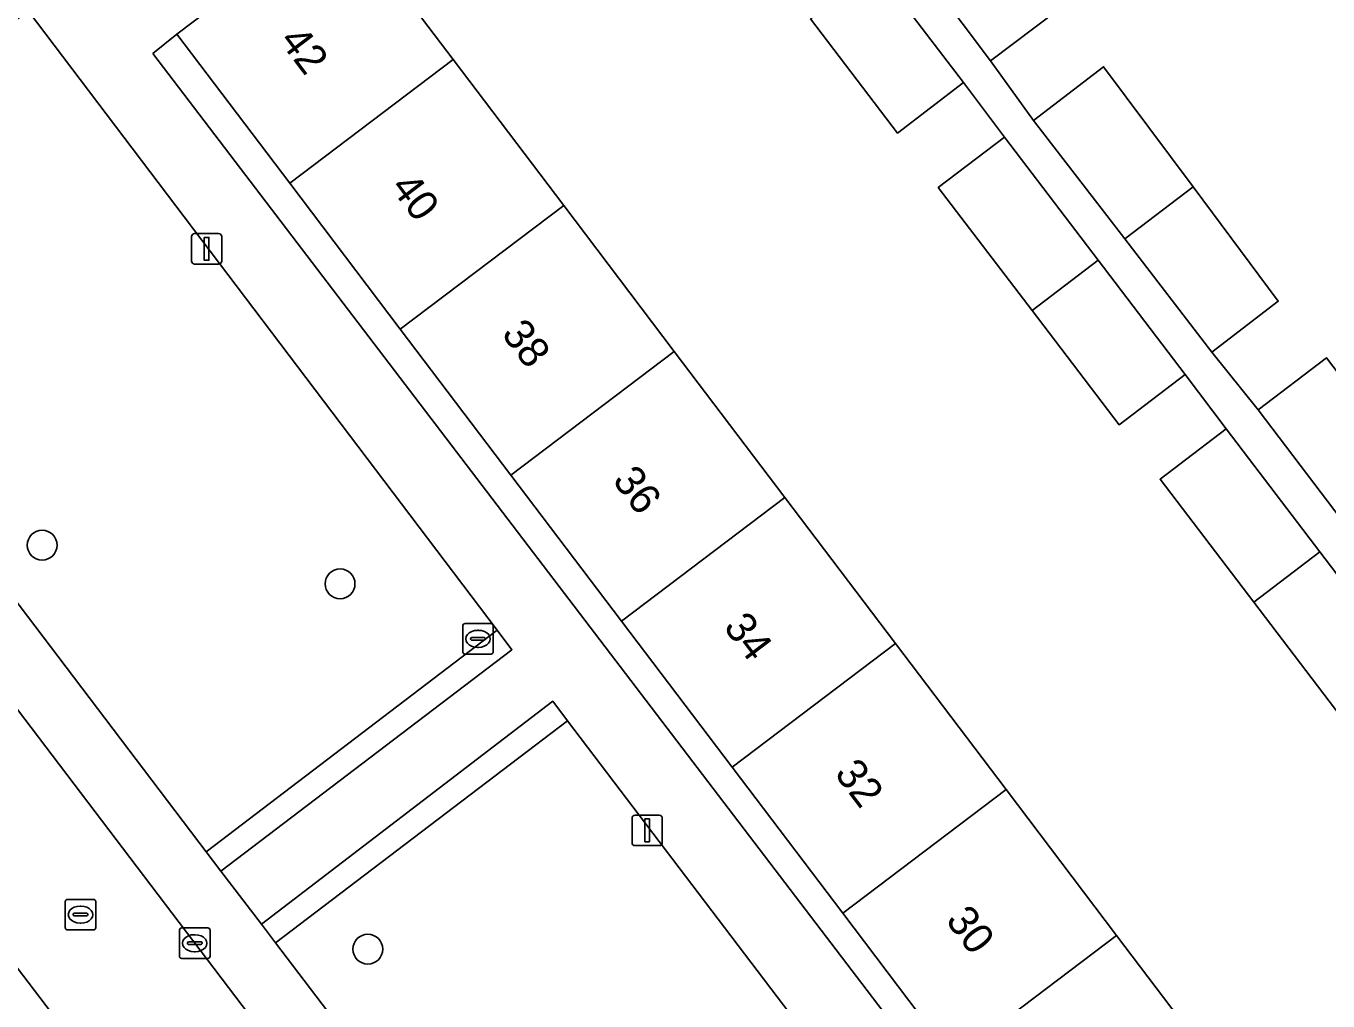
# Model space of a CAD drawing. Extents: x 160030 to 160839, y 385325 to 386450.
# Drawn here: x 160322.65 to 160365.28, y 385818.69 to 385850.63 of the extents above; entities that cross this region are included whole.
import ezdxf

# ---------------------------------------------------------------- set-up
doc = ezdxf.new("R2010")
doc.units = 0
for name, color, linetype in [('IMGEO_Boom', 7, 'Continuous'), ('IMGEO_Erf', 7, 'Continuous'), ('IMGEO_Groenvoorziening', 7, 'Continuous'), ('IMGEO_Haag', 7, 'Continuous'), ('IMGEO_Kolk', 7, 'Continuous'), ('IMGEO_Lichtmast', 7, 'Continuous'), ('IMGEO_Pand', 7, 'Continuous'), ('IMGEO_Pand_nummerreeks', 7, 'Continuous'), ('IMGEO_Parkeervlak_open', 7, 'Continuous'), ('IMGEO_Rijbaan_lokaal_open', 7, 'Continuous'), ('IMGEO_Rioolput', 7, 'Continuous'), ('IMGEO_Voetpad_open', 7, 'Continuous')]:
    doc.layers.add(name, color=color, linetype=linetype)

msp = doc.modelspace()

# ---------------------------------------------------------------- linework, layer by layer
at = {"layer": 'IMGEO_Boom'}
for centre in [(160323.173, 385833.623), (160332.93, 385832.357), (160333.839, 385820.388)]:
    msp.add_circle(centre, 0.489, dxfattribs=at)
at = {"layer": 'IMGEO_Erf'}
for points in [[(160368.302, 385851), (160364.692, 385855.793), (160361.083, 385860.586), (160357.473, 385865.379), (160355.064, 385863.555), (160351.36, 385868.446), (160346.224, 385864.537), (160349.141, 385860.685), (160347.132, 385859.164), (160348.447, 385857.175), (160350.654, 385858.838), (160353.608, 385854.917), (160356.441, 385851.157), (160354.234, 385849.495), (160355.644, 385847.541), (160357.933, 385849.297), (160360.866, 385845.359), (160363.656, 385841.612), (160361.48, 385839.942), (160362.994, 385838.058), (160365.235, 385839.759), (160366.479, 385838.119)], [(160332.936, 385854.418), (160336.632, 385849.537), (160340.253, 385844.754), (160343.875, 385839.97), (160347.497, 385835.186), (160351.119, 385830.403), (160354.741, 385825.619), (160358.362, 385820.836), (160361.985, 385816.052)], [(160365.707, 385828.014), (160362.851, 385831.759), (160359.782, 385835.783), (160361.946, 385837.433), (160360.61, 385839.22), (160358.447, 385837.57), (160355.591, 385841.315), (160352.522, 385845.339), (160354.686, 385846.989), (160353.35, 385848.776), (160351.187, 385847.126), (160348.331, 385850.871)]]:
    msp.add_lwpolyline(points, dxfattribs=at)
msp.add_lwpolyline([(160326.797, 385849.728), (160363.321, 385801.798), (160363.952, 385802.336), (160360.255, 385807.219), (160356.634, 385812.002), (160353.011, 385816.786), (160349.39, 385821.569), (160345.768, 385826.353), (160342.146, 385831.137), (160338.524, 385835.92), (160334.902, 385840.704), (160331.281, 385845.487), (160327.586, 385850.367)], close=True, dxfattribs=at)
at = {"layer": 'IMGEO_Groenvoorziening'}
msp.add_lwpolyline([(160321.143, 385833.325), (160328.543, 385823.58), (160338.075, 385830.835), (160322.717, 385851.129), (160316.136, 385846.137)], dxfattribs=at)
for points in [[(160329.027, 385822.942), (160338.558, 385830.197), (160338.075, 385830.835), (160328.543, 385823.58)], [(160330.818, 385820.592), (160340.379, 385827.87), (160339.895, 385828.507), (160330.354, 385821.202)], [(160340.379, 385827.87), (160330.818, 385820.592), (160336.136, 385813.601), (160337.195, 385814.406), (160337.554, 385813.934), (160339.814, 385810.964), (160348.315, 385817.419)]]:
    msp.add_lwpolyline(points, close=True, dxfattribs=at)
at = {"layer": 'IMGEO_Haag'}
for points in [[(160329.027, 385822.942), (160338.558, 385830.197), (160338.075, 385830.835), (160328.543, 385823.58)], [(160330.818, 385820.592), (160340.379, 385827.87), (160339.895, 385828.507), (160330.354, 385821.202)]]:
    msp.add_lwpolyline(points, close=True, dxfattribs=at)
at = {"layer": 'IMGEO_Kolk'}
for p, q in [((160327.67, 385820.156), (160327.67, 385821.008)), ((160327.745, 385821.082), (160328.597, 385821.082)), ((160328.671, 385821.008), (160328.671, 385820.156)), ((160327.929, 385820.576), (160327.929, 385820.588)), ((160328.367, 385820.539), (160327.969, 385820.539)), ((160327.972, 385820.625), (160328.37, 385820.625)), ((160328.158, 385820.862), (160328.183, 385820.862)), ((160328.413, 385820.588), (160328.413, 385820.576)), ((160328.597, 385820.082), (160327.745, 385820.082)), ((160328.181, 385820.302), (160328.156, 385820.302))]:
    msp.add_line(p, q, dxfattribs=at)
for points in [[(160327.67, 385820.156), (160327.67, 385821.008)], [(160327.745, 385821.082), (160328.597, 385821.082)], [(160328.671, 385821.008), (160328.671, 385820.156)], [(160328.597, 385820.082), (160327.745, 385820.082)]]:
    msp.add_lwpolyline(points, dxfattribs=at)
for centre, radius, start, end in [((160327.747, 385821.006), 0.0765, 91.552, 178.448), ((160327.747, 385821.006), 0.0765, 91.552, 178.448), ((160328.595, 385821.006), 0.0765, 1.552, 88.448), ((160328.595, 385821.006), 0.0765, 1.552, 88.448), ((160327.969, 385820.585), 0.0403, 85.8775, 175.7526), ((160327.966, 385820.575), 0.0366, 178.938, 274.7102), ((160328.37, 385820.582), 0.043, 264.8664, 352.4533), ((160328.374, 385820.587), 0.0386, 1.7309, 96.639), ((160327.747, 385820.158), 0.0765, 181.552, 268.448), ((160327.747, 385820.158), 0.0765, 181.552, 268.448), ((160328.595, 385820.158), 0.0765, 271.552, 358.448), ((160328.595, 385820.158), 0.0765, 271.552, 358.448)]:
    msp.add_arc(centre, radius, start, end, dxfattribs=at)
for centre, major_axis, ratio, start_param, end_param in [((160328.157, 385820.582), (-0.387, 0.002), 0.722429, 4.712389, 7.853982), ((160328.182, 385820.582), (-0.39, 0.002), 0.717154, 1.570796, 4.712389)]:
    msp.add_ellipse(centre, major_axis=major_axis, ratio=ratio, start_param=start_param, end_param=end_param, dxfattribs=at)
at = {"layer": 'IMGEO_Lichtmast'}
for p, q in [((160328.064, 385842.933), (160328.064, 385843.733)), ((160328.064, 385843.733), (160328.064, 385842.933)), ((160328.164, 385843.833), (160328.954, 385843.833)), ((160328.954, 385843.833), (160328.164, 385843.833)), ((160329.054, 385843.733), (160329.054, 385842.933)), ((160329.054, 385842.933), (160329.054, 385843.733)), ((160328.954, 385842.833), (160328.164, 385842.833)), ((160328.164, 385842.833), (160328.954, 385842.833)), ((160342.591, 385824.779), (160343.381, 385824.779)), ((160343.381, 385824.779), (160342.591, 385824.779)), ((160342.491, 385823.879), (160342.491, 385824.679)), ((160342.491, 385824.679), (160342.491, 385823.879)), ((160343.481, 385824.679), (160343.481, 385823.879)), ((160343.481, 385823.879), (160343.481, 385824.679)), ((160343.381, 385823.779), (160342.591, 385823.779)), ((160342.591, 385823.779), (160343.381, 385823.779))]:
    msp.add_line(p, q, dxfattribs=at)
for points in [[(160328.484, 385843.708), (160328.634, 385843.708), (160328.634, 385842.958), (160328.484, 385842.958), (160328.484, 385843.708)], [(160342.911, 385824.654), (160343.061, 385824.654), (160343.061, 385823.904), (160342.911, 385823.904), (160342.911, 385824.654)]]:
    msp.add_lwpolyline(points, dxfattribs=at)
for centre, start, end in [((160328.164, 385843.733), 90, 180), ((160328.164, 385843.733), 90, 180), ((160328.954, 385843.733), 0, 90), ((160328.954, 385843.733), 360, 90), ((160328.164, 385842.933), 180, 270), ((160328.164, 385842.933), 180, 270), ((160328.954, 385842.933), 270, 0), ((160328.954, 385842.933), 270, 0), ((160342.591, 385824.679), 90, 180), ((160342.591, 385824.679), 90, 180), ((160343.381, 385824.679), 0, 90), ((160343.381, 385824.679), 360, 90), ((160342.591, 385823.879), 180, 270), ((160342.591, 385823.879), 180, 270), ((160343.381, 385823.879), 270, 0), ((160343.381, 385823.879), 270, 0)]:
    msp.add_arc(centre, 0.1, start, end, dxfattribs=at)
at = {"layer": 'IMGEO_Pand'}
for points in [[(160351.409, 385853.245), (160354.234, 385849.495), (160356.441, 385851.157), (160353.608, 385854.917)], [(160327.586, 385850.367), (160331.281, 385845.487), (160336.632, 385849.537), (160332.936, 385854.418)], [(160348.331, 385850.871), (160351.187, 385847.126), (160353.35, 385848.776), (160350.5, 385852.513)], [(160331.281, 385845.487), (160334.902, 385840.704), (160340.253, 385844.754), (160336.632, 385849.537)], [(160357.933, 385849.297), (160355.644, 385847.541), (160358.628, 385843.658), (160360.866, 385845.359)], [(160357.76, 385842.957), (160354.686, 385846.989), (160352.522, 385845.339), (160355.591, 385841.315)], [(160360.866, 385845.359), (160358.628, 385843.658), (160361.48, 385839.942), (160363.656, 385841.612)], [(160343.875, 385839.97), (160340.253, 385844.754), (160334.902, 385840.704), (160338.524, 385835.92)], [(160355.591, 385841.315), (160358.447, 385837.57), (160360.61, 385839.22), (160357.76, 385842.957)], [(160338.524, 385835.92), (160342.146, 385831.137), (160347.497, 385835.186), (160343.875, 385839.97)], [(160368.047, 385839.309), (160366.479, 385838.119), (160365.235, 385839.759), (160362.994, 385838.058), (160365.957, 385834.154), (160368.195, 385835.854), (160368.123, 385835.949), (160369.693, 385837.14)], [(160365.02, 385833.401), (160361.946, 385837.433), (160359.782, 385835.783), (160362.851, 385831.759)], [(160351.119, 385830.403), (160347.497, 385835.186), (160342.146, 385831.137), (160345.768, 385826.353)], [(160365.02, 385833.401), (160362.851, 385831.759), (160365.707, 385828.014), (160367.775, 385829.591), (160367.87, 385829.664)], [(160345.768, 385826.353), (160349.39, 385821.569), (160354.741, 385825.619), (160351.119, 385830.403)], [(160358.362, 385820.836), (160354.741, 385825.619), (160349.39, 385821.569), (160353.011, 385816.786)], [(160361.985, 385816.052), (160358.362, 385820.836), (160353.011, 385816.786), (160356.634, 385812.002)]]:
    msp.add_lwpolyline(points, close=True, dxfattribs=at)
at = {"layer": 'IMGEO_Parkeervlak_open'}
for points in [[(160317.059, 385835.221), (160339.626, 385805.488)], [(160329.027, 385822.942), (160328.543, 385823.58), (160321.143, 385833.325)], [(160338.999, 385809.839), (160336.498, 385813.126), (160336.136, 385813.601), (160330.818, 385820.592), (160330.354, 385821.202), (160329.027, 385822.942)]]:
    msp.add_lwpolyline(points, dxfattribs=at)
at = {"layer": 'IMGEO_Rijbaan_lokaal_open'}
for points in [[(160308.883, 385837.678), (160322.339, 385819.813), (160334.964, 385803.193)], [(160341.22, 385803.374), (160341.021, 385803.649), (160339.626, 385805.488), (160317.059, 385835.221), (160315.009, 385837.923)]]:
    msp.add_lwpolyline(points, dxfattribs=at)
at = {"layer": 'IMGEO_Rioolput'}
for p, q in [((160336.947, 385830.127), (160336.947, 385830.979)), ((160337.022, 385831.053), (160337.874, 385831.053)), ((160337.435, 385830.833), (160337.46, 385830.833)), ((160337.948, 385830.979), (160337.948, 385830.127)), ((160337.206, 385830.547), (160337.206, 385830.559)), ((160337.644, 385830.51), (160337.246, 385830.51)), ((160337.249, 385830.596), (160337.647, 385830.596)), ((160337.458, 385830.273), (160337.433, 385830.273)), ((160337.69, 385830.559), (160337.69, 385830.547)), ((160337.874, 385830.053), (160337.022, 385830.053)), ((160323.93, 385821.093), (160323.93, 385821.945)), ((160324.005, 385822.019), (160324.857, 385822.019)), ((160324.418, 385821.799), (160324.443, 385821.799)), ((160324.931, 385821.945), (160324.931, 385821.093)), ((160324.189, 385821.513), (160324.189, 385821.525)), ((160324.627, 385821.476), (160324.229, 385821.476)), ((160324.232, 385821.562), (160324.63, 385821.562)), ((160324.673, 385821.525), (160324.673, 385821.513)), ((160324.857, 385821.019), (160324.005, 385821.019)), ((160324.441, 385821.239), (160324.416, 385821.239))]:
    msp.add_line(p, q, dxfattribs=at)
for points in [[(160336.947, 385830.127), (160336.947, 385830.979)], [(160337.022, 385831.053), (160337.874, 385831.053)], [(160337.948, 385830.979), (160337.948, 385830.127)], [(160337.874, 385830.053), (160337.022, 385830.053)], [(160323.93, 385821.093), (160323.93, 385821.945)], [(160324.005, 385822.019), (160324.857, 385822.019)], [(160324.931, 385821.945), (160324.931, 385821.093)], [(160324.857, 385821.019), (160324.005, 385821.019)]]:
    msp.add_lwpolyline(points, dxfattribs=at)
for centre, radius, start, end in [((160337.024, 385830.977), 0.0765, 91.552, 178.448), ((160337.024, 385830.977), 0.0765, 91.552, 178.448), ((160337.872, 385830.977), 0.0765, 1.552, 88.448), ((160337.872, 385830.977), 0.0765, 1.552, 88.448), ((160337.246, 385830.556), 0.0403, 85.8775, 175.7526), ((160337.243, 385830.546), 0.0366, 178.938, 274.7102), ((160337.647, 385830.553), 0.043, 264.8664, 352.4533), ((160337.651, 385830.558), 0.0386, 1.7309, 96.639), ((160337.024, 385830.129), 0.0765, 181.552, 268.448), ((160337.024, 385830.129), 0.0765, 181.552, 268.448), ((160337.872, 385830.129), 0.0765, 271.552, 358.448), ((160337.872, 385830.129), 0.0765, 271.552, 358.448), ((160324.007, 385821.943), 0.0765, 91.552, 178.448), ((160324.007, 385821.943), 0.0765, 91.552, 178.448), ((160324.855, 385821.943), 0.0765, 1.552, 88.448), ((160324.855, 385821.943), 0.0765, 1.552, 88.448), ((160324.229, 385821.522), 0.0403, 85.8775, 175.7526), ((160324.226, 385821.512), 0.0366, 178.938, 274.7102), ((160324.63, 385821.519), 0.043, 264.8664, 352.4533), ((160324.634, 385821.524), 0.0386, 1.7309, 96.639), ((160324.007, 385821.095), 0.0765, 181.552, 268.448), ((160324.007, 385821.095), 0.0765, 181.552, 268.448), ((160324.855, 385821.095), 0.0765, 271.552, 358.448), ((160324.855, 385821.095), 0.0765, 271.552, 358.448)]:
    msp.add_arc(centre, radius, start, end, dxfattribs=at)
for centre, major_axis, ratio, start_param, end_param in [((160337.434, 385830.553), (-0.387, 0.002), 0.722429, 4.712389, 7.853982), ((160337.459, 385830.553), (-0.39, 0.002), 0.717154, 1.570796, 4.712389), ((160324.417, 385821.519), (-0.387, 0.002), 0.722429, 4.712389, 7.853982), ((160324.442, 385821.519), (-0.39, 0.002), 0.717154, 1.570796, 4.712389)]:
    msp.add_ellipse(centre, major_axis=major_axis, ratio=ratio, start_param=start_param, end_param=end_param, dxfattribs=at)
at = {"layer": 'IMGEO_Voetpad_open'}
for points in [[(160326.797, 385849.728), (160327.586, 385850.367), (160332.936, 385854.418), (160340.997, 385860.55), (160342.953, 385862.032), (160344.216, 385863.016), (160346.224, 385864.537), (160351.36, 385868.446), (160353.782, 385870.28), (160354.522, 385870.841), (160353.622, 385872.023), (160361.189, 385877.731)], [(160365.957, 385834.154), (160362.994, 385838.058), (160361.48, 385839.942), (160358.628, 385843.658), (160355.644, 385847.541), (160354.234, 385849.495), (160351.409, 385853.245), (160348.447, 385857.175), (160347.132, 385859.164), (160344.216, 385863.016), (160342.953, 385862.032), (160345.903, 385858.136), (160347.23, 385856.396), (160347.426, 385856.545), (160350.5, 385852.513), (160353.35, 385848.776), (160354.686, 385846.989), (160357.76, 385842.957), (160360.61, 385839.22), (160361.946, 385837.433), (160365.02, 385833.401), (160367.87, 385829.664)], [(160326.328, 385853.868), (160322.717, 385851.129), (160338.075, 385830.835), (160338.558, 385830.197), (160329.027, 385822.942), (160330.354, 385821.202), (160339.895, 385828.507), (160340.379, 385827.87), (160348.315, 385817.419), (160348.774, 385816.814), (160348.92, 385816.623), (160349.301, 385816.12), (160349.785, 385815.482), (160352.475, 385811.94), (160355.177, 385808.382)], [(160359.872, 385800.912), (160360.29, 385800.291), (160360.696, 385799.757), (160363.321, 385801.798), (160326.797, 385849.728)], [(160334.964, 385803.193), (160322.339, 385819.813), (160308.883, 385837.678)]]:
    msp.add_lwpolyline(points, dxfattribs=at)

# ---------------------------------------------------------------- texts
at = {"layer": 'IMGEO_Pand_nummerreeks'}
for s, p in [('42', (160330.913, 385850.148)), ('40', (160334.553, 385845.34)), ('38', (160338.19, 385840.537)), ('36', (160341.824, 385835.737)), ('34', (160345.461, 385830.934)), ('32', (160349.096, 385826.132)), ('30', (160352.736, 385821.324))]:
    msp.add_text(s, height=1, rotation=307.1307, dxfattribs=at).set_placement(p)

doc.saveas('drawing.dxf')
